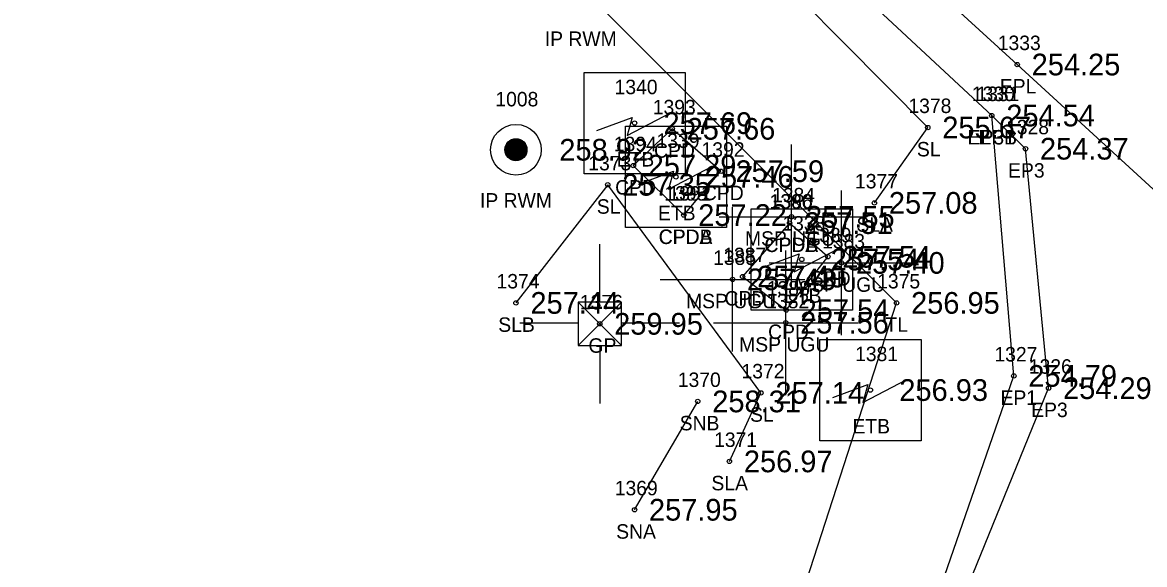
# Model space of a CAD drawing. Extents: x 1961231 to 1962574, y 799865 to 801120.
# Drawn here: x 1961948.3 to 1962025.9, y 800468.6 to 800506.1 of the extents above; entities that cross this region are included whole.
import ezdxf

# ---------------------------------------------------------------- set-up
doc = ezdxf.new("R2010")
doc.units = 0
for name, color, linetype in [('RD_EX_BldgApp', 7, 'Continuous'), ('RD_EX_BldgApp_txCode', 7, 'Continuous'), ('RD_EX_Conc', 7, 'Continuous'), ('RD_EX_Conc_txCode', 7, 'Continuous'), ('RD_EX_DV_Prop_txCode', 7, 'Continuous'), ('RD_EX_DV_PropPin', 7, 'Continuous'), ('RD_EX_Misc', 7, 'Continuous'), ('RD_EX_Misc_txCode', 7, 'Continuous'), ('RD_EX_Road', 7, 'Continuous'), ('RD_EX_Road_txCode', 7, 'Continuous'), ('RD_EX_TX_BldgApp_ELEV', 7, 'Continuous'), ('RD_EX_TX_Conc_ELEV', 7, 'Continuous'), ('RD_EX_TX_DV_Prop_ELEV', 7, 'Continuous'), ('RD_EX_TX_Misc_ELEV', 7, 'Continuous'), ('RD_EX_TX_Road_ELEV', 7, 'Continuous'), ('RD_EX_TX_UT_ELEV', 7, 'Continuous'), ('RD_EX_TX_VEG_ELEV', 7, 'Continuous'), ('RD_EX_UT', 7, 'Continuous'), ('RD_EX_UT_txCode', 7, 'Continuous'), ('RD_EX_VEG', 7, 'Continuous'), ('RD_EX_VEG_txCode', 7, 'Continuous'), ('RD_SMD_Locator', 7, 'Continuous')]:
    doc.layers.add(name, color=color, linetype=linetype)

msp = doc.modelspace()

# ---------------------------------------------------------------- linework, layer by layer
at = {"layer": 'RD_EX_BldgApp'}
msp.add_line((1961990.595, 800472.386), (1961994.973, 800479.877), dxfattribs=at)
at = {"layer": 'RD_EX_Conc'}
for points in [[(1961994.002, 800492.764), (1961996.578, 800495.798), (1961993.201, 800498.73), (1961990.507, 800496.182), (1961994.002, 800492.764)], [(1962001.321, 800492.21), (1961998.074, 800488.508), (1962001.088, 800486.194), (1962003.975, 800489.882), (1962001.321, 800492.21)]]:
    msp.add_lwpolyline(points, dxfattribs=at)
at = {"layer": 'RD_EX_DV_PropPin'}
for p, q in [((1961981.832, 800496.765), (1961981.832, 800497.795)), ((1961981.867, 800496.729), (1961981.867, 800497.831)), ((1961981.902, 800496.698), (1961981.902, 800497.862)), ((1961981.937, 800496.67), (1961981.937, 800497.89)), ((1961981.972, 800496.645), (1961981.972, 800497.914)), ((1961982.007, 800496.624), (1961982.007, 800497.936)), ((1961982.042, 800496.604), (1961982.042, 800497.956)), ((1961982.077, 800496.587), (1961982.077, 800497.973)), ((1961982.112, 800496.572), (1961982.112, 800497.987)), ((1961982.147, 800496.559), (1961982.147, 800498)), ((1961982.182, 800496.548), (1961982.182, 800498.011)), ((1961982.217, 800496.539), (1961982.217, 800498.021)), ((1961982.252, 800496.532), (1961982.252, 800498.028)), ((1961982.287, 800496.526), (1961982.287, 800498.034)), ((1961982.322, 800496.522), (1961982.322, 800498.038)), ((1961982.357, 800496.52), (1961982.357, 800498.04)), ((1961982.392, 800496.519), (1961982.392, 800498.041)), ((1961982.427, 800496.52), (1961982.427, 800498.04)), ((1961982.462, 800496.522), (1961982.462, 800498.038)), ((1961982.497, 800496.526), (1961982.497, 800498.034)), ((1961982.532, 800496.532), (1961982.532, 800498.028)), ((1961982.567, 800496.539), (1961982.567, 800498.021)), ((1961982.602, 800496.548), (1961982.602, 800498.011)), ((1961982.637, 800496.559), (1961982.637, 800498)), ((1961982.672, 800496.572), (1961982.672, 800497.987)), ((1961982.708, 800496.587), (1961982.708, 800497.973)), ((1961982.743, 800496.604), (1961982.743, 800497.956)), ((1961982.778, 800496.624), (1961982.778, 800497.936)), ((1961982.813, 800496.645), (1961982.813, 800497.914)), ((1961982.848, 800496.67), (1961982.848, 800497.89)), ((1961982.883, 800496.698), (1961982.883, 800497.862)), ((1961982.918, 800496.729), (1961982.918, 800497.831)), ((1961982.953, 800496.765), (1961982.953, 800497.795)), ((1961981.657, 800497.084), (1961981.657, 800497.476)), ((1961981.692, 800496.982), (1961981.692, 800497.578)), ((1961981.727, 800496.91), (1961981.727, 800497.649)), ((1961981.762, 800496.853), (1961981.762, 800497.706)), ((1961981.797, 800496.806), (1961981.797, 800497.754)), ((1961982.988, 800496.806), (1961982.988, 800497.754)), ((1961983.023, 800496.853), (1961983.023, 800497.706)), ((1961983.058, 800496.91), (1961983.058, 800497.649)), ((1961983.093, 800496.982), (1961983.093, 800497.578)), ((1961983.128, 800497.084), (1961983.128, 800497.476))]:
    msp.add_line(p, q, dxfattribs=at)
for radius in [1.75, 0.761]:
    msp.add_circle((1961982.392, 800497.28), radius, dxfattribs=at)
at = {"layer": 'RD_EX_Misc'}
for p, q in [((1962001.456, 800487.643), (1962001.456, 800497.643)), ((1962004.916, 800484.458), (1962004.916, 800494.458)), ((1961997.379, 800483.319), (1961997.379, 800493.319)), ((1961996.456, 800492.643), (1962006.456, 800492.643)), ((1962001.054, 800480.321), (1962001.054, 800490.321)), ((1961999.916, 800489.458), (1962009.916, 800489.458)), ((1961992.379, 800488.319), (1962002.379, 800488.319)), ((1961996.054, 800485.321), (1962006.054, 800485.321))]:
    msp.add_line(p, q, dxfattribs=at)
at = {"layer": 'RD_EX_Road'}
for points in [[(1962241.795, 800315.68), (1962238.351, 800317.597), (1962189.917, 800352.695), (1962151.637, 800383.489), (1962113.782, 800416.386), (1962074.109, 800451.288), (1962034.784, 800486.956), (1962017.07, 800503.174), (1961999.461, 800519.248), (1961962.476, 800552.117), (1961937.077, 800573.106), (1961923.189, 800584.904), (1961883.072, 800617.432), (1961838.294, 800653.432), (1961801.423, 800682.572), (1961728.409, 800740.856), (1961722.948, 800745.107), (1961689.132, 800771.929)], [(1961992.53, 800418.336), (1962000.944, 800437), (1962011.011, 800464.808), (1962016.837, 800481.64), (1962015.313, 800499.647), (1961996.985, 800516.713), (1961979.472, 800530.761), (1961969.799, 800538.748), (1961958.277, 800547.161), (1961941.067, 800560.824), (1961925.414, 800573.413), (1961918.19, 800579.247), (1961879.318, 800611.179), (1961866.074, 800621.075), (1961838.294, 800653.432)], [(1962000.944, 800437), (1962012.341, 800463.86), (1962019.243, 800480.795), (1962017.644, 800497.353), (1962015.313, 800499.647)]]:
    msp.add_lwpolyline(points, dxfattribs=at)
at = {"layer": 'RD_EX_UT'}
for p, q in [((1961988.188, 800486.744), (1961988.188, 800490.744)), ((1961989.688, 800486.744), (1961986.688, 800483.744)), ((1961986.688, 800486.744), (1961989.688, 800483.744)), ((1961989.688, 800486.744), (1961986.688, 800486.744)), ((1961986.688, 800486.744), (1961986.688, 800483.744)), ((1961989.688, 800483.744), (1961989.688, 800486.744)), ((1961986.663, 800485.292), (1961982.663, 800485.292)), ((1961989.702, 800485.31), (1961993.718, 800485.31)), ((1961986.688, 800483.744), (1961989.688, 800483.744)), ((1961988.188, 800483.744), (1961988.188, 800479.744))]:
    msp.add_line(p, q, dxfattribs=at)
for points in [[(1961987.101, 800495.623), (1961987.101, 800502.623), (1961994.101, 800502.623), (1961994.101, 800495.623)], [(1961989.962, 800491.907), (1961989.962, 800498.907), (1961996.962, 800498.907), (1961996.962, 800491.907)], [(1961998.669, 800486.194), (1961998.669, 800493.194), (1962005.669, 800493.194), (1962005.669, 800486.194)], [(1962003.416, 800477.164), (1962003.416, 800484.164), (1962010.416, 800484.164), (1962010.416, 800477.164)]]:
    msp.add_lwpolyline(points, close=True, dxfattribs=at)
for points in [[(1961987.999, 800498.617), (1961990.421, 800499.517), (1961990.075, 800498.27), (1961993.12, 800499.863)], [(1961990.86, 800494.901), (1961993.282, 800495.801), (1961992.936, 800494.555), (1961995.982, 800496.148)], [(1961999.567, 800489.188), (1962001.989, 800490.088), (1962001.643, 800488.842), (1962004.688, 800490.434)], [(1962004.314, 800480.158), (1962006.737, 800481.058), (1962006.391, 800479.812), (1962009.436, 800481.405)]]:
    msp.add_lwpolyline(points, dxfattribs=at)
at = {"layer": 'RD_EX_VEG'}
for points in [[(1961986.163, 800417.052), (1962008.727, 800486.692), (1961986.141, 800509.275), (1961949.4, 800540.421), (1961909.418, 800571.418), (1961867.438, 800598.729), (1961825.041, 800634.775), (1961788.236, 800662.233), (1961745.486, 800697.377)], [(1962007.192, 800493.608), (1962010.887, 800498.82), (1961996.296, 800513.539), (1961988.624, 800510.004)], [(1961997.16, 800475.73), (1961999.342, 800480.471), (1961988.744, 800494.857), (1961982.395, 800486.689)]]:
    msp.add_lwpolyline(points, dxfattribs=at)
at = {"layer": 'RD_SMD_Locator'}
for centre in [(1962017.07, 800503.174), (1962015.313, 800499.647), (1962015.313, 800499.647), (1961990.601, 800499.123), (1961993.201, 800498.73), (1962010.887, 800498.82), (1961982.392, 800497.28), (1962017.644, 800497.353), (1961990.507, 800496.182), (1961993.462, 800495.407), (1961996.578, 800495.798), (1961988.744, 800494.857), (1962007.192, 800493.608), (1961994.002, 800492.764), (1961994.002, 800492.764), (1962001.321, 800492.21), (1962001.321, 800492.21), (1962001.456, 800492.643), (1962003.975, 800489.882), (1962002.169, 800489.694), (1962004.916, 800489.458), (1961998.074, 800488.508), (1961997.379, 800488.319), (1961982.395, 800486.689), (1962001.088, 800486.194), (1962008.727, 800486.692), (1961988.188, 800485.244), (1962001.054, 800485.321), (1962016.837, 800481.64), (1962006.916, 800480.664), (1962019.243, 800480.795), (1961994.973, 800479.877), (1961999.342, 800480.471), (1961997.16, 800475.73), (1961990.595, 800472.386)]:
    msp.add_circle(centre, 0.15, dxfattribs=at)

# ---------------------------------------------------------------- texts
at = {"layer": 'RD_EX_BldgApp_txCode'}
for s, p in [('1370', (1961993.587, 800480.877)), ('SNB', (1961993.721, 800477.877)), ('1369', (1961989.225, 800473.386)), ('SNA', (1961989.327, 800470.386))]:
    msp.add_text(s, height=1, dxfattribs=at).set_placement(p)
at = {"layer": 'RD_EX_Conc_txCode'}
for s, p in [('1393', (1961991.855, 800499.73)), ('1394', (1961989.16, 800497.182)), ('1392', (1961995.232, 800496.798)), ('CPD', (1961991.949, 800496.73)), ('CPD', (1961989.255, 800494.182)), ('1395', (1961992.656, 800493.764)), ('1391', (1961992.939, 800493.764)), ('CPD', (1961995.326, 800493.798)), ('1390', (1961999.935, 800493.21)), ('1386', (1961999.951, 800493.21)), ('CPDA', (1961992.262, 800490.764)), ('CPDB', (1961992.278, 800490.764)), ('1389', (1962002.628, 800490.882)), ('CPDA', (1961999.581, 800490.21)), ('CPDB', (1961999.597, 800490.21)), ('1387', (1961996.727, 800489.508)), ('CPD', (1962002.723, 800487.882)), ('1388', (1961999.741, 800487.194)), ('CPD', (1961996.822, 800486.508)), ('CPD', (1961999.836, 800484.194))]:
    msp.add_text(s, height=1, dxfattribs=at).set_placement(p)
at = {"layer": 'RD_EX_DV_Prop_txCode'}
for s, p in [('IP RWM', (1961984.387, 800504.46)), ('1008', (1961980.967, 800500.28)), ('IP RWM', (1961979.904, 800493.28))]:
    msp.add_text(s, height=1, dxfattribs=at).set_placement(p)
at = {"layer": 'RD_EX_Misc_txCode'}
for s, p in [('1384', (1962000.109, 800493.643)), ('MSP UGU', (1961998.235, 800490.643)), ('1383', (1962003.569, 800490.458)), ('1385', (1961996.032, 800489.319)), ('MSP UGU', (1962001.695, 800487.458)), ('MSP UGU', (1961994.158, 800486.319)), ('1382', (1961999.707, 800486.321)), ('MSP UGU', (1961997.833, 800483.321))]:
    msp.add_text(s, height=1, dxfattribs=at).set_placement(p)
at = {"layer": 'RD_EX_Road_txCode'}
for s, p in [('1333', (1962015.724, 800504.174)), ('EPL', (1962015.866, 800501.174)), ('1330', (1962013.927, 800500.647)), ('1331', (1962014.25, 800500.647)), ('1328', (1962016.297, 800498.353)), ('EP3B', (1962013.636, 800497.647)), ('EP1', (1962014.392, 800497.647)), ('EP3', (1962016.439, 800495.353)), ('1327', (1962015.491, 800482.64)), ('1326', (1962017.873, 800481.795)), ('EP1', (1962015.916, 800479.64)), ('EP3', (1962018.038, 800478.795))]:
    msp.add_text(s, height=1, dxfattribs=at).set_placement(p)
at = {"layer": 'RD_EX_TX_BldgApp_ELEV'}
for s, p in [('258.31', (1961995.973, 800479.127)), ('257.95', (1961991.595, 800471.636))]:
    msp.add_text(s, height=1.5, dxfattribs=at).set_placement(p)
at = {"layer": 'RD_EX_TX_Conc_ELEV'}
for s, p in [('257.66', (1961994.201, 800497.98)), ('257.29', (1961991.507, 800495.432)), ('257.59', (1961997.578, 800495.048)), ('257.22', (1961995.002, 800492.014)), ('257.22', (1961995.002, 800492.014)), ('257.51', (1962002.321, 800491.46)), ('257.51', (1962002.321, 800491.46)), ('257.54', (1962004.975, 800489.132)), ('257.49', (1961999.074, 800487.758)), ('257.54', (1962002.088, 800485.444))]:
    msp.add_text(s, height=1.5, dxfattribs=at).set_placement(p)
at = {"layer": 'RD_EX_TX_DV_Prop_ELEV'}
msp.add_text('258.92', height=1.5, dxfattribs=at).set_placement((1961985.392, 800496.53))
at = {"layer": 'RD_EX_TX_Misc_ELEV'}
for s, p in [('257.55', (1962002.456, 800491.893)), ('257.40', (1962005.916, 800488.708)), ('257.43', (1961998.379, 800487.569)), ('257.56', (1962002.054, 800484.571))]:
    msp.add_text(s, height=1.5, dxfattribs=at).set_placement(p)
at = {"layer": 'RD_EX_TX_Road_ELEV'}
for s, p in [('254.25', (1962018.07, 800502.424)), ('254.54', (1962016.313, 800498.897)), ('254.54', (1962016.313, 800498.897)), ('254.37', (1962018.644, 800496.603)), ('254.79', (1962017.837, 800480.89)), ('254.29', (1962020.243, 800480.045))]:
    msp.add_text(s, height=1.5, dxfattribs=at).set_placement(p)
at = {"layer": 'RD_EX_TX_UT_ELEV'}
for s, p in [('257.69', (1961992.601, 800498.373)), ('257.46', (1961995.462, 800494.657)), ('257.54', (1962004.169, 800488.944)), ('259.95', (1961989.188, 800484.494)), ('256.93', (1962008.916, 800479.914))]:
    msp.add_text(s, height=1.5, dxfattribs=at).set_placement(p)
at = {"layer": 'RD_EX_TX_VEG_ELEV'}
for s, p in [('255.67', (1962011.887, 800498.07)), ('257.35', (1961989.744, 800494.107)), ('257.08', (1962008.192, 800492.858)), ('257.44', (1961983.395, 800485.939)), ('256.95', (1962009.727, 800485.942)), ('257.14', (1962000.342, 800479.721)), ('256.97', (1961998.16, 800474.98))]:
    msp.add_text(s, height=1.5, dxfattribs=at).set_placement(p)
at = {"layer": 'RD_EX_UT_txCode'}
for s, p in [('1340', (1961989.215, 800501.123)), ('1339', (1961992.115, 800497.407)), ('ETB', (1961989.356, 800496.123)), ('ETB', (1961992.218, 800492.407)), ('1338', (1962000.822, 800491.694)), ('1376', (1961986.817, 800486.244)), ('ETB', (1962000.924, 800486.694)), ('GP', (1961987.408, 800483.244)), ('1381', (1962005.853, 800482.664)), ('ETB', (1962005.672, 800477.664))]:
    msp.add_text(s, height=1, dxfattribs=at).set_placement(p)
at = {"layer": 'RD_EX_VEG_txCode'}
for s, p in [('1378', (1962009.541, 800499.82)), ('SL', (1962010.131, 800496.82)), ('1373', (1961987.397, 800495.857)), ('1377', (1962005.846, 800494.608)), ('SL', (1961987.988, 800492.857)), ('SLA', (1962005.948, 800491.608)), ('1374', (1961981.049, 800487.689)), ('1375', (1962007.38, 800487.692)), ('SLB', (1961981.167, 800484.689)), ('TL', (1962007.955, 800484.692)), ('1372', (1961997.995, 800481.471)), ('SL', (1961998.586, 800478.471)), ('1371', (1961996.097, 800476.73)), ('SLA', (1961995.916, 800473.73))]:
    msp.add_text(s, height=1, dxfattribs=at).set_placement(p)

doc.saveas('drawing.dxf')
